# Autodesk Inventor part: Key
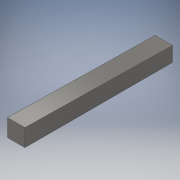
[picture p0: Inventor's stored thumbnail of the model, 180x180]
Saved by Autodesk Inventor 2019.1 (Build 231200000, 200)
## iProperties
Created: 2020-03
Part Number: Key
Material: Stainless Steel, 440C
Document SubType Name: Modeling
Designer: Oghenemarho
Density: 7.75 g/cm^3
Appearance: Semi-Polished
Author: Oghenemarho
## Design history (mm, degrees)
sketch "Sketch1"
  geometry: L1 (-2.997, -2.997)-(2.997, -2.997); L2 (2.997, -2.997)-(2.997, 2.997); L3 (2.997, 2.997)-(-2.997, 2.997); L4 (-2.997, 2.997)-(-2.997, -2.997); L5 (-2.997, -2.997)-(2.997, 2.997); L6 (2.997, -2.997)-(-2.997, 2.997); 1 further point
  constraints: 12 end point, 2 midpoint, 2 parallel, 1 horizontal, 1 perpendicular
  dimensions: "d0" = 5.9944 distance of L3.end L2.end; "d1" = 5.9944 distance of L2.end L1.end
extrude "Extrusion1" new body sketch "Sketch1" distance "d2" = 50.8; taper "d3" = 0 deg
feature "FaceDraft1" dims angle "d4" = 1 deg
body "Solid1"
